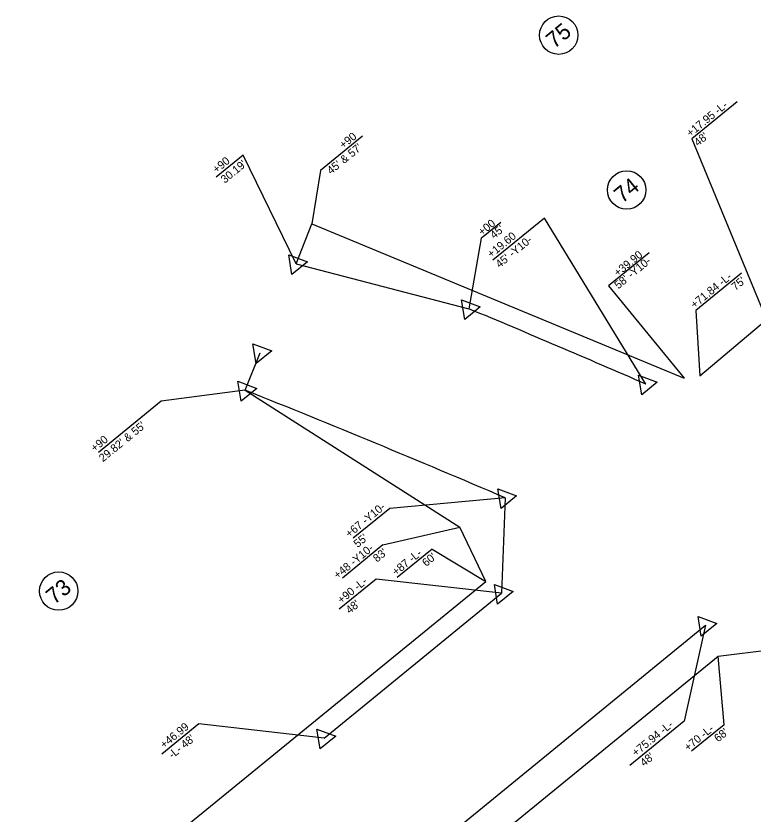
# Model space of a CAD drawing. Extents: x 2320946 to 2332748, y 597838 to 612698.
# Drawn here: x 2326056.5 to 2326516.9, y 601758.6 to 602257.2 of the extents above; entities that cross this region are included whole.
import ezdxf

# ---------------------------------------------------------------- set-up
doc = ezdxf.new("R2010")
doc.units = 0
for name, color, linetype in [('Prop Easement Construction', 7, 'Continuous'), ('Prop Easement Construction Station Offsets', 7, 'Continuous'), ('Prop Parcel Number CELL', 7, 'Continuous'), ('Prop ROW Marker CELL', 7, 'Continuous'), ('Prop ROW RW Lines', 7, 'Continuous'), ('Prop ROW Station Offsets', 7, 'Continuous')]:
    doc.layers.add(name, color=color, linetype=linetype)

msp = doc.modelspace()

# ---------------------------------------------------------------- linework, layer by layer
at = {"layer": 'Prop Easement Construction'}
for p, q in [((2326483.68, 602032.45), (2326738.6, 602247.02)), ((2326231.46, 602102.47), (2326241.44, 602127.36)), ((2326241.44, 602127.36), (2326473.95, 602030.93)), ((2326199.77, 602023.4), (2326333.87, 601937.79)), ((2326349.99, 601903.94), (2326333.87, 601937.79)), ((2326061.82, 601668.68), (2326349.99, 601903.94)), ((2326495.23, 601857.27), (2326548.1, 601863.86)), ((2326156.72, 601580.91), (2326495.23, 601857.27))]:
    msp.add_line(p, q, dxfattribs=at)
at = {"layer": 'Prop Easement Construction Station Offsets'}
for p, q in [((2326273, 602182.14), (2326246.75, 602160.71)), ((2326451.97, 602109.27), (2326426.67, 602088.62)), ((2326509.66, 602096.47), (2326481.21, 602073.25)), ((2326285.78, 601926.73), (2326260.48, 601906.08)), ((2326316.45, 601924.02), (2326294.74, 601906.3)), ((2326498.87, 601814.36), (2326478.6, 601797.82))]:
    msp.add_line(p, q, dxfattribs=at)
for points in [[(2326246.75, 602160.71), (2326241.41, 602127.29)], [(2326426.67, 602088.62), (2326473.95, 602030.93)], [(2326481.21, 602073.25), (2326483.68, 602032.45)], [(2326285.78, 601926.73), (2326333.87, 601937.79)], [(2326316.45, 601924.02), (2326349.99, 601903.94)], [(2326498.87, 601814.36), (2326495.23, 601857.27)]]:
    msp.add_lwpolyline(points, dxfattribs=at)
at = {"layer": 'Prop Parcel Number CELL'}
for p, q in [((2326395.57, 602245.25), (2326395.57, 602245.25)), ((2326438.02, 602148.52), (2326438.02, 602148.52)), ((2326083.23, 601897.9), (2326083.23, 601897.9))]:
    msp.add_line(p, q, dxfattribs=at)
for centre in [(2326395.57, 602245.25), (2326438.02, 602148.52), (2326083.23, 601897.9)]:
    msp.add_circle(centre, 12, dxfattribs=at)
at = {"layer": 'Prop ROW Marker CELL'}
for p, q in [((2326231.46, 602102.47), (2326231.46, 602102.47)), ((2326339.37, 602074.34), (2326339.37, 602074.34)), ((2326209.14, 602046.78), (2326209.14, 602046.78)), ((2326450.03, 602027.19), (2326450.03, 602027.19)), ((2326199.77, 602023.4), (2326199.77, 602023.4)), ((2326362.17, 601956.18), (2326362.17, 601956.18)), ((2326359.9, 601896.54), (2326359.9, 601896.54)), ((2326487.18, 601876.52), (2326487.18, 601876.52)), ((2326249.12, 601806.1), (2326249.12, 601806.1))]:
    msp.add_line(p, q, dxfattribs=at)
for points in [[(2326228.9, 602095.73), (2326226.91, 602108.05), (2326238.58, 602103.63)], [(2326336.81, 602067.6), (2326334.82, 602079.92), (2326346.49, 602075.51)], [(2326206.58, 602040.03), (2326204.59, 602052.35), (2326216.26, 602047.94)], [(2326447.46, 602020.45), (2326445.47, 602032.77), (2326457.15, 602028.36)], [(2326197.21, 602016.66), (2326195.22, 602028.98), (2326206.89, 602024.56)], [(2326359.6, 601949.43), (2326357.61, 601961.75), (2326369.28, 601957.34)], [(2326357.34, 601889.8), (2326355.35, 601902.11), (2326367.02, 601897.7)], [(2326484.62, 601869.78), (2326482.63, 601882.1), (2326494.3, 601877.68)], [(2326246.56, 601799.36), (2326244.57, 601811.68), (2326256.24, 601807.26)]]:
    msp.add_lwpolyline(points, close=True, dxfattribs=at)
at = {"layer": 'Prop ROW RW Lines'}
for p, q in [((2326199.77, 602023.4), (2326209.14, 602046.78)), ((2326362.17, 601956.18), (2326359.9, 601896.54)), ((2326249.12, 601806.1), (2326359.9, 601896.54)), ((2326056.53, 601524.94), (2326487.18, 601876.52))]:
    msp.add_line(p, q, dxfattribs=at)
for radius, start, end in [(7915, 66.485701, 67.356427), (7815, 66.868648, 68.157257)]:
    msp.add_arc((2323292.12, 594769.45), radius, start, end, dxfattribs=at)
at = {"layer": 'Prop ROW Station Offsets'}
for p, q in [((2326507.06, 602203.63), (2326478.62, 602180.4)), ((2326198.49, 602170.28), (2326181.53, 602156.44)), ((2326231.46, 602102.47), (2326198.49, 602170.28)), ((2326386.71, 602130.99), (2326354.43, 602104.62)), ((2326450.03, 602027.19), (2326386.71, 602130.99)), ((2326359.3, 602128.29), (2326348.33, 602119.33)), ((2326231.46, 602102.47), (2326339.37, 602074.34)), ((2326199.77, 602023.4), (2326147.29, 602016.54)), ((2326147.29, 602016.54), (2326108.09, 601984.54)), ((2326362.17, 601956.18), (2326289.99, 601949.6)), ((2326289.99, 601949.6), (2326267.18, 601930.98)), ((2326281.53, 601905.41), (2326258.41, 601886.54)), ((2326359.9, 601896.54), (2326281.53, 601905.41)), ((2326487.18, 601876.52), (2326473.88, 601816.71)), ((2326473.88, 601816.71), (2326439.99, 601789.03)), ((2326170.75, 601814.97), (2326147.63, 601796.1)), ((2326249.12, 601806.1), (2326170.75, 601814.97))]:
    msp.add_line(p, q, dxfattribs=at)
for points in [[(2326478.62, 602180.4), (2326536.48, 602040.69)], [(2326348.33, 602119.33), (2326347.12, 602118.34), (2326339.37, 602074.34)]]:
    msp.add_lwpolyline(points, dxfattribs=at)

# ---------------------------------------------------------------- texts
at = {"layer": 'Prop Easement Construction Station Offsets'}
for s, p in [('+90 ', (2326261.02, 602173.97)), ("45' & 57'", (2326253.3, 602157.99)), ('+39.90', (2326432.45, 602094.15)), ("58' -Y10-", (2326432.8, 602086.36)), ('+71.84 -L-', (2326480.42, 602074.22)), ("75'", (2326505.95, 602085.38)), ('+48 -Y10-', (2326257.45, 601905.22)), ("83'", (2326282.07, 601915.64)), ('+87 -L-', (2326293.95, 601907.27)), ("60'", (2326312.75, 601912.93)), ('+70 -L-', (2326476.36, 601797.6)), ("68'", (2326495.16, 601803.27))]:
    msp.add_text(s, height=5, rotation=39.228, dxfattribs=at).set_placement(p)
at = {"layer": 'Prop Parcel Number CELL'}
for s, p in [('75', (2326392.76, 602236.5)), ('74', (2326435.27, 602139.82)), ('73', (2326080.44, 601889.16))]:
    msp.add_text(s, height=10, rotation=39.228, dxfattribs=at).set_placement(p)
at = {"layer": 'Prop ROW Station Offsets'}
for s, p in [('+17.95 -L-', (2326477.83, 602181.37)), ("48'", (2326482.57, 602175.56)), ('+90 ', (2326181.84, 602158.68)), ("30.19'", (2326186.98, 602152.39)), ('+00', (2326347.71, 602119.63)), ("45'", (2326355.2, 602117.68)), ('+19.60', (2326353.45, 602105.83)), ("45' -Y10-", (2326358.58, 602099.53)), ("29.82' & 55'", (2326110.86, 601978.31)), ('+90 ', (2326105.73, 601984.6)), ('+67 -Y10-', (2326264.81, 601931.04)), ("55'", (2326269.95, 601924.75)), ('+90 -L-', (2326259.85, 601889.71)), ("48'", (2326264.99, 601883.41)), ('+46.99', (2326149.07, 601799.27)), ('+75.94 -L-', (2326443.76, 601794.31)), ("-L- 48'", (2326154.21, 601792.97)), ("48'", (2326448.9, 601788.02))]:
    msp.add_text(s, height=5, rotation=39.228, dxfattribs=at).set_placement(p)

doc.saveas('drawing.dxf')
